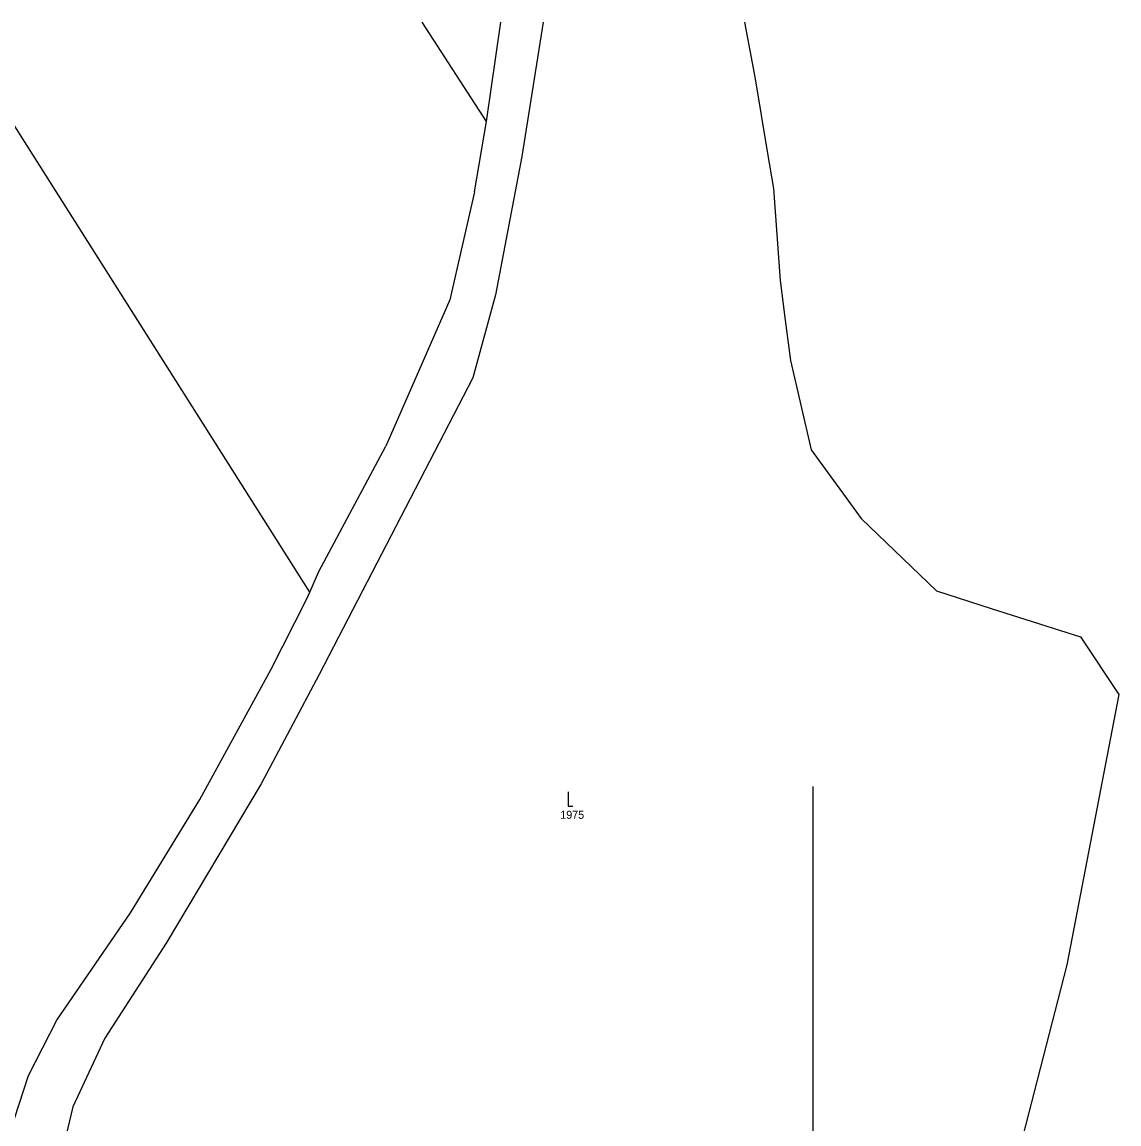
# Model space of a CAD drawing. Extents: x -801853 to -800578, y -1017479 to -1016338.
# Drawn here: x -801418.1 to -801185.1, y -1016571.7 to -1016337.6 of the extents above; entities that cross this region are included whole.
import ezdxf

# ---------------------------------------------------------------- set-up
doc = ezdxf.new("R2010")
doc.units = 0
for name, color, linetype in [('Default', 7, 'Continuous'), ('KLADY_ZMVM', 7, 'Continuous'), ('KN_HRANICE', 7, 'Continuous'), ('KN_KULTURY', 7, 'Continuous'), ('KN_PARCELY', 7, 'Continuous')]:
    doc.layers.add(name, color=color, linetype=linetype)

# ---------------------------------------------------------------- blocks, each defined once
blk = doc.blocks.new('302')
at = {"layer": 'Default'}
blk.add_lwpolyline([(0, 3), (0, 0), (1, 0)], dxfattribs=at)

msp = doc.modelspace()

# ---------------------------------------------------------------- linework, layer by layer
at = {"layer": 'KLADY_ZMVM'}
msp.add_line((-801250, -1017000), (-801250, -1016500), dxfattribs=at)
at = {"layer": 'KN_HRANICE'}
for p, q in [((-801356.93, -1016458.73), (-801433.65, -1016337.63)), ((-801319.43, -1016358.75), (-801333.04, -1016337.63)), ((-801319.43, -1016358.75), (-801316.33, -1016337.63)), ((-801307.4, -1016337.63), (-801311.92, -1016366.18)), ((-801264.62, -1016337.63), (-801262.33, -1016349.67)), ((-801262.33, -1016349.67), (-801259.75, -1016365.1)), ((-801321.94, -1016373.73), (-801319.43, -1016358.75)), ((-801311.92, -1016366.18), (-801317.51, -1016395.6)), ((-801259.75, -1016365.1), (-801258.44, -1016372.97)), ((-801258.44, -1016372.97), (-801257.05, -1016392.52)), ((-801321.94, -1016373.73), (-801327.21, -1016396.62)), ((-801257.05, -1016392.52), (-801255.96, -1016400.96)), ((-801327.21, -1016396.62), (-801340.82, -1016427.74)), ((-801317.51, -1016395.6), (-801322.34, -1016413.23)), ((-801255.96, -1016400.96), (-801254.86, -1016409.5)), ((-801254.86, -1016409.5), (-801250.45, -1016428.49)), ((-801322.34, -1016413.23), (-801326.45, -1016421.12)), ((-801326.45, -1016421.12), (-801354.97, -1016476.24)), ((-801355.05, -1016454.39), (-801340.82, -1016427.74)), ((-801250.45, -1016428.49), (-801242.64, -1016439.22)), ((-801242.64, -1016439.22), (-801239.82, -1016443.1)), ((-801239.82, -1016443.1), (-801223.83, -1016458.49)), ((-801356.93, -1016458.73), (-801355.05, -1016454.39)), ((-801357.62, -1016460.33), (-801356.93, -1016458.73)), ((-801223.83, -1016458.49), (-801212.17, -1016462.19)), ((-801365.17, -1016475.08), (-801357.62, -1016460.33)), ((-801212.17, -1016462.19), (-801193.22, -1016468.21)), ((-801193.22, -1016468.21), (-801185.05, -1016480.49)), ((-801380.3, -1016502.77), (-801365.17, -1016475.08)), ((-801354.97, -1016476.24), (-801367.28, -1016499.46)), ((-801185.05, -1016480.49), (-801196.12, -1016537.94)), ((-801367.28, -1016499.46), (-801387.43, -1016533.33)), ((-801395.02, -1016526.89), (-801380.3, -1016502.77)), ((-801410.71, -1016549.67), (-801395.02, -1016526.89)), ((-801387.43, -1016533.33), (-801400.48, -1016553.49)), ((-801196.12, -1016537.94), (-801207.69, -1016582.91)), ((-801416.73, -1016561.43), (-801410.71, -1016549.67)), ((-801400.48, -1016553.49), (-801407.27, -1016568.09)), ((-801419.68, -1016570.55), (-801416.73, -1016561.43)), ((-801407.27, -1016568.09), (-801410.39, -1016580.85))]:
    msp.add_line(p, q, dxfattribs=at)

# ---------------------------------------------------------------- block references
at = {"layer": 'KN_KULTURY'}
msp.add_blockref('302', (-801302.09, -1016504.19), dxfattribs=at)

# ---------------------------------------------------------------- texts
at = {"layer": 'KN_PARCELY'}
msp.add_text('1975', height=1.7, dxfattribs=at).set_placement((-801303.73, -1016506.89))

doc.saveas('drawing.dxf')
